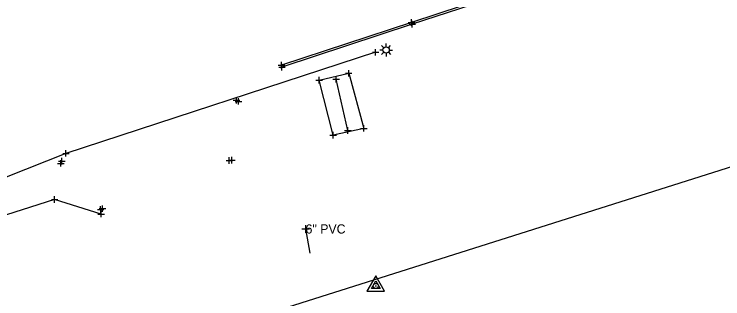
# Model space of a CAD drawing. Extents: x 1729655 to 1739338, y 463812 to 469501.
# Drawn here: x 1734985 to 1735123.5, y 466865.3 to 466921 of the extents above; entities that cross this region are included whole.
import ezdxf

# ---------------------------------------------------------------- set-up
doc = ezdxf.new("R2010")
doc.units = 0
for name, color, linetype in [('S_Bridge_Column_Round', 7, 'Continuous'), ('S_Bridge_Deck', 7, 'Continuous'), ('S_Bridge_ExpansionJoint', 7, 'Continuous'), ('S_Drainage_Invert_Culvert', 7, 'Continuous'), ('S_Ground_SpotElevation', 7, 'Continuous'), ('S_Property_RockBoulder', 7, 'Continuous'), ('S_RetWall_Top', 7, 'Continuous'), ('S_Terrain_Boundary', 7, 'Continuous'), ('S_Terrain_High_Points', 7, 'Continuous'), ('S_Terrain_Imported_Contours', 7, 'Continuous'), ('S_Traffic_Sign_SinglePost', 7, 'Continuous'), ('S_Utilities_Pole_StreetLight', 7, 'Continuous'), ('S_Utilities_UG_Sanitary_MH', 7, 'Continuous')]:
    doc.layers.add(name, color=color, linetype=linetype)

msp = doc.modelspace()

# ---------------------------------------------------------------- linework, layer by layer
at = {"layer": 'S_Bridge_Column_Round'}
for p, q in [((1735062.02, 466919.39), (1735063.3, 466919.39)), ((1735062.19, 466919.04), (1735063.47, 466919.04)), ((1735062.66, 466918.75), (1735062.66, 466920.03)), ((1735062.66, 466919.39), (1735062.66, 466919.39)), ((1735062.83, 466918.4), (1735062.83, 466919.68)), ((1735062.83, 466919.04), (1735062.83, 466919.04)), ((1735055.02, 466913.55), (1735056.29, 466913.55)), ((1735055.66, 466912.91), (1735055.65, 466914.19)), ((1735055.65, 466913.55), (1735055.65, 466913.55)), ((1735036.62, 466911.02), (1735037.89, 466911.02)), ((1735037.25, 466910.39), (1735037.25, 466911.66)), ((1735037.25, 466911.02), (1735037.25, 466911.02)), ((1735037.35, 466909.99), (1735037.35, 466911.26)), ((1735036.71, 466910.62), (1735037.98, 466910.63)), ((1735037.35, 466910.63), (1735037.35, 466910.63)), ((1735049.76, 466909.45), (1735051.03, 466909.45)), ((1735050.4, 466908.81), (1735050.39, 466910.08)), ((1735050.4, 466909.45), (1735050.4, 466909.45)), ((1735043.96, 466908.1), (1735045.24, 466908.1)), ((1735044.6, 466907.47), (1735044.6, 466908.74)), ((1735044.6, 466908.1), (1735044.6, 466908.1)), ((1735047.3, 466908.27), (1735048.57, 466908.28)), ((1735047.93, 466907.64), (1735047.93, 466908.91)), ((1735047.93, 466908.27), (1735047.93, 466908.27)), ((1735027.83, 466904.16), (1735029.1, 466904.16)), ((1735028.2, 466903.94), (1735029.48, 466903.95)), ((1735028.46, 466903.53), (1735028.46, 466904.8)), ((1735028.46, 466904.16), (1735028.46, 466904.16)), ((1735028.84, 466903.31), (1735028.84, 466904.58)), ((1735028.84, 466903.94), (1735028.84, 466903.94)), ((1735050.21, 466897.61), (1735050.21, 466898.89)), ((1735052.71, 466898.67), (1735053.98, 466898.67)), ((1735053.34, 466898.03), (1735053.34, 466899.3)), ((1735053.34, 466898.67), (1735053.34, 466898.67)), ((1735046.73, 466897.34), (1735048.01, 466897.34)), ((1735047.37, 466896.7), (1735047.37, 466897.98)), ((1735047.37, 466897.34), (1735047.37, 466897.34)), ((1735049.58, 466898.25), (1735050.85, 466898.25)), ((1735050.21, 466898.25), (1735050.21, 466898.25)), ((1734995.12, 466893.16), (1734995.12, 466894.43)), ((1734994.31, 466891.62), (1734994.31, 466892.89)), ((1734994.48, 466893.79), (1734995.75, 466893.79)), ((1734995.12, 466893.79), (1734995.12, 466893.79)), ((1735027.05, 466891.77), (1735027.05, 466893.04)), ((1735027.54, 466891.82), (1735027.54, 466893.09)), ((1734993.46, 466891.82), (1734994.74, 466891.83)), ((1734993.67, 466892.25), (1734994.94, 466892.26)), ((1734994.1, 466891.19), (1734994.1, 466892.46)), ((1734994.1, 466891.83), (1734994.1, 466891.83)), ((1734994.31, 466892.25), (1734994.31, 466892.25)), ((1735026.42, 466892.41), (1735027.69, 466892.41)), ((1735026.9, 466892.45), (1735028.18, 466892.45)), ((1735027.05, 466892.41), (1735027.05, 466892.41)), ((1735027.54, 466892.45), (1735027.54, 466892.45)), ((1734992.26, 466884.76), (1734993.53, 466884.76)), ((1734992.9, 466884.12), (1734992.89, 466885.4)), ((1734992.89, 466884.76), (1734992.89, 466884.76)), ((1735001.91, 466882.19), (1735001.9, 466883.47)), ((1735001.91, 466882.19), (1735001.9, 466883.47)), ((1735002.25, 466882.35), (1735002.25, 466883.62)), ((1735002.25, 466882.35), (1735002.25, 466883.62)), ((1735001.27, 466882.83), (1735002.54, 466882.83)), ((1735001.27, 466882.83), (1735002.54, 466882.83)), ((1735001.35, 466881.91), (1735002.63, 466881.92)), ((1735001.62, 466882.98), (1735002.89, 466882.99)), ((1735001.62, 466882.98), (1735002.89, 466882.99)), ((1735001.91, 466882.83), (1735001.91, 466882.83)), ((1735001.91, 466882.83), (1735001.91, 466882.83)), ((1735001.99, 466881.28), (1735001.99, 466882.55)), ((1735001.99, 466881.92), (1735001.99, 466881.92)), ((1735002.25, 466882.98), (1735002.25, 466882.98)), ((1735002.25, 466882.98), (1735002.25, 466882.98))]:
    msp.add_line(p, q, dxfattribs=at)
at = {"layer": 'S_Bridge_Deck'}
for p, q in [((1735057.7, 466914.62), (1735057.7, 466915.24)), ((1735057.08, 466913.99), (1735056.46, 466913.99)), ((1735057.26, 466914.43), (1735056.82, 466914.87)), ((1735057.26, 466913.55), (1735056.82, 466913.11)), ((1735058.14, 466914.43), (1735058.59, 466914.87)), ((1735058.14, 466913.55), (1735058.59, 466913.11)), ((1735058.33, 466913.99), (1735058.95, 466913.99)), ((1735057.7, 466913.37), (1735057.7, 466912.74))]:
    msp.add_line(p, q, dxfattribs=at)
msp.add_circle((1735057.7, 466913.99), 0.624, dxfattribs=at)
at = {"layer": 'S_Bridge_ExpansionJoint'}
for p, q in [((1735041.21, 466879.01), (1735042.71, 466879.01)), ((1735041.96, 466879.76), (1735041.96, 466878.26))]:
    msp.add_line(p, q, dxfattribs=at)
at = {"layer": 'S_Drainage_Invert_Culvert'}
msp.add_lwpolyline([(1735001.99, 466881.92), (1734992.89, 466884.76), (1734961.21, 466874.67), (1734936.56, 466867.99), (1734933.3, 466874.09), (1734937.2, 466881.06)], dxfattribs=at)
at = {"layer": 'S_Ground_SpotElevation'}
for p, q in [((1735092.82, 466929.33), (1735062.66, 466919.39)), ((1735062.66, 466919.39), (1735037.25, 466911.02))]:
    msp.add_line(p, q, dxfattribs=at)
at = {"layer": 'S_Property_RockBoulder'}
msp.add_lwpolyline([(1735050.21, 466898.25), (1735047.93, 466908.27)], dxfattribs=at)
at = {"layer": 'S_RetWall_Top'}
for p, q in [((1735216.98, 466920.25), (1734990.13, 466848.42)), ((1735041.96, 466879.01), (1735042.8, 466874.29))]:
    msp.add_line(p, q, dxfattribs=at)
at = {"layer": 'S_Terrain_Boundary'}
for p, q in [((1735055.56, 466867.86), (1735055.81, 466867.86)), ((1735055.69, 466867.98), (1735055.69, 466867.73))]:
    msp.add_line(p, q, dxfattribs=at)
msp.add_lwpolyline([(1735053.96, 466866.86), (1735057.42, 466866.86), (1735055.69, 466869.85)], close=True, dxfattribs=at)
msp.add_circle((1735055.69, 466867.86), 0.499, dxfattribs=at)
at = {"layer": 'S_Terrain_Imported_Contours'}
msp.add_line((1735055.69, 466867.86), (1735055.69, 466867.86), dxfattribs=at)
msp.add_lwpolyline([(1735054.82, 466867.36), (1735055.69, 466868.86), (1735056.56, 466867.36)], close=True, dxfattribs=at)
msp.add_circle((1735055.69, 466867.86), 0.5, dxfattribs=at)
at = {"layer": 'S_Traffic_Sign_SinglePost'}
msp.add_lwpolyline([(1735044.6, 466908.1), (1735050.4, 466909.45), (1735053.34, 466898.67), (1735047.37, 466897.34)], close=True, dxfattribs=at)
at = {"layer": 'S_Utilities_Pole_StreetLight'}
msp.add_lwpolyline([(1735055.65, 466913.55), (1734995.12, 466893.79), (1734932.25, 466868.87), (1734850.4, 466839.95)], dxfattribs=at)
at = {"layer": 'S_Utilities_UG_Sanitary_MH'}
for p, q in [((1735089.35, 466927.72), (1735062.83, 466919.04)), ((1735062.83, 466919.04), (1735037.35, 466910.63))]:
    msp.add_line(p, q, dxfattribs=at)

# ---------------------------------------------------------------- texts
at = {"layer": 'S_Terrain_High_Points'}
msp.add_text('6" PVC', height=1.8, dxfattribs=at).set_placement((1735041.96, 466878.11))

doc.saveas('drawing.dxf')
